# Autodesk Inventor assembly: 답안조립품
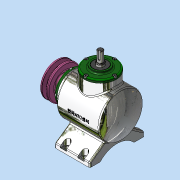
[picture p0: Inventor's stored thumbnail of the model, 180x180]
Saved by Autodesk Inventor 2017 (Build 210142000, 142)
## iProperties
Part Number: 답안조립품
Material: 일반
Document SubType Name: Assembly
Designer: MRC
Author: MRC
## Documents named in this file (17)
- C:\Users\MRC\Desktop\730108V1001\답안조립품.iam
- C:\Users\MRC\Desktop\730108V1001\V-벨트풀리.ipt
- C:\Users\MRC\Desktop\730108V1001\메인 베벨기어.ipt
- C:\Users\MRC\Desktop\730108V1001\메인 축.ipt
- 메인 축.ipt
- C:\Users\MRC\Desktop\730108V1001\베어링 6203.ipt
- C:\Users\MRC\Desktop\730108V1001\본체.ipt
- C:\Users\MRC\Desktop\730108V1001\볼트 M4 x 10.ipt
- C:\Users\MRC\Desktop\730108V1001\서브 베벨기어.ipt
- C:\Users\MRC\Desktop\730108V1001\서브 축.ipt
- 서브 축.ipt
- C:\Users\MRC\Desktop\730108V1001\오일실 17 x 32 x 8.ipt
- C:\Users\MRC\Desktop\730108V1001\와셔 4 x 16.ipt
- C:\Users\MRC\Desktop\730108V1001\육각볼트 M4 x 8.ipt
- C:\Users\MRC\Desktop\730108V1001\커버.ipt
- C:\Users\MRC\Desktop\730108V1001\키 4 x 4 x 14.ipt
- C:\Users\MRC\Desktop\730108V1001\키 5 x 5 x 14.ipt
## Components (1 placed, 1 different names)
1. V-벨트풀리:1
